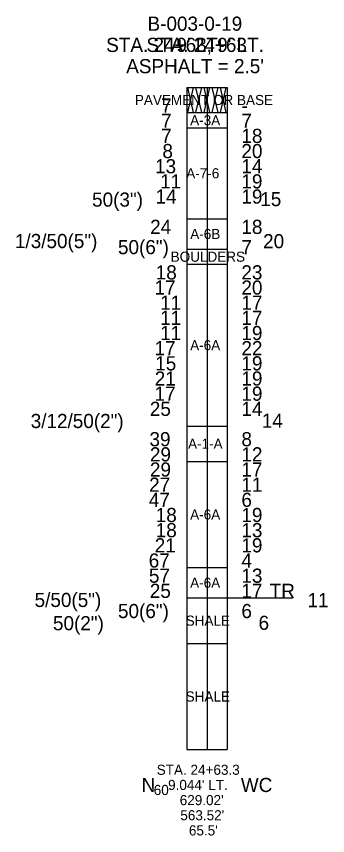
# Model space of a CAD drawing. Extents: x -1.89 to 1.19, y -7.4 to 0.7.
import ezdxf

# ---------------------------------------------------------------- set-up
doc = ezdxf.new("R2010")
doc.units = 0
for name, color, linetype in [('GT_Project_Soil_Boring', 7, 'Continuous'), ('GT_Project_Soil_Layers', 7, 'Continuous'), ('GT_Project_Text', 7, 'Continuous'), ('GT_Project_Text_2', 7, 'Continuous'), ('GT_Project_Text_3', 7, 'Continuous'), ('SC_Scratch1', 7, 'Continuous'), ('SC_Scratch2', 7, 'Continuous'), ('SC_Scratch3', 7, 'Continuous')]:
    doc.layers.add(name, color=color, linetype=linetype)

msp = doc.modelspace()

# ---------------------------------------------------------------- linework, layer by layer
at = {"layer": 'GT_Project_Soil_Boring'}
for points in [[(-0.2, 0), (0.2, 0)], [(-0.2, 0), (-0.2, -6.55)], [(0, 0), (0, -6.55)], [(0.2, 0), (0.2, -6.55)], [(-0.2, -0.25), (0.2, -0.25)], [(-0.2, -0.4), (0.2, -0.4)], [(-0.2, -1.3), (0.2, -1.3)], [(-0.2, -1.6), (0.2, -1.6)], [(-0.2, -1.75), (0.2, -1.75)], [(-0.2, -3.35), (0.2, -3.35)], [(-0.2, -3.7), (0.2, -3.7)], [(-0.2, -4.75), (0.2, -4.75)], [(-0.2, -5.05), (0.2, -5.05)], [(-0.2, -5.5), (0.2, -5.5)], [(-0.2, -6.55), (0.2, -6.55)]]:
    msp.add_lwpolyline(points, dxfattribs=at)
at = {"layer": 'GT_Project_Soil_Layers'}
for p, q in [((-0.1906, -0.25), (-0.1329, 0.0001)), ((-0.1329, -0.25), (-0.1906, 0.0001)), ((-0.1098, -0.25), (-0.052, 0.0001)), ((-0.052, -0.25), (-0.1098, 0.0001)), ((-0.0289, -0.25), (0.0288, 0.0001)), ((0.0288, -0.25), (-0.0289, 0.0001)), ((0.0519, -0.25), (0.1096, 0.0001)), ((0.1096, -0.25), (0.0519, 0.0001)), ((0.1327, -0.25), (0.1904, 0.0001)), ((0.1904, -0.25), (0.1327, 0.0001)), ((-0.2001, -0.25), (-0.2001, -0.25))]:
    msp.add_line(p, q, dxfattribs=at)
at = {"layer": 'GT_Project_Text'}
msp.add_line((-0.5272, -6.9), (-0.5272, -6.9), dxfattribs=at)
msp.add_lwpolyline([(0.2, -5.05), (0.85, -5.05)], dxfattribs=at)

# ---------------------------------------------------------------- texts
for s, height, p in [('B-003-0-19', 0.14, (-0.5886, 0.56)), ("ASPHALT = 2.5'", 0.14, (-0.7997, 0.14)), ('7', 0.14, (-0.4535, -0.25)), ('-', 0.14, (0.34, -0.25)), ('7', 0.14, (-0.4535, -0.4)), ('7', 0.14, (0.34, -0.4)), ('7', 0.14, (-0.4535, -0.55)), ('18', 0.14, (0.34, -0.55)), ('8', 0.14, (-0.4414, -0.7)), ('20', 0.14, (0.34, -0.7)), ('13', 0.14, (-0.5141, -0.85)), ('14', 0.14, (0.34, -0.85)), ('11', 0.14, (-0.4643, -1)), ('19', 0.14, (0.34, -1)), ('50(3")', 0.14, (-1.1372, -1.18)), ('14', 0.14, (-0.5097, -1.15)), ('19', 0.14, (0.34, -1.15)), ('15', 0.14, (0.5269, -1.175)), ('24', 0.14, (-0.5627, -1.45)), ('18', 0.14, (0.34, -1.45)), ('1/3/50(5")', 0.14, (-1.9005, -1.59)), ('20', 0.14, (0.5549, -1.5917)), ('50(6")', 0.14, (-0.8812, -1.65)), ('7', 0.14, (0.34, -1.65)), ('18', 0.14, (-0.5075, -1.9)), ('23', 0.14, (0.34, -1.9)), ('17', 0.14, (-0.5196, -2.05)), ('20', 0.14, (0.34, -2.05)), ('11', 0.14, (-0.4643, -2.2)), ('17', 0.14, (0.34, -2.2)), ('11', 0.14, (-0.4643, -2.35)), ('17', 0.14, (0.34, -2.35)), ('11', 0.14, (-0.4643, -2.5)), ('19', 0.14, (0.34, -2.5)), ('17', 0.14, (-0.5196, -2.65)), ('22', 0.14, (0.34, -2.65)), ('15', 0.14, (-0.513, -2.8)), ('19', 0.14, (0.34, -2.8)), ('21', 0.14, (-0.5173, -2.95)), ('19', 0.14, (0.34, -2.95)), ('17', 0.14, (-0.5196, -3.1)), ('19', 0.14, (0.34, -3.1)), ('25', 0.14, (-0.566, -3.25)), ('14', 0.14, (0.34, -3.25)), ('3/12/50(2")', 0.14, (-1.7445, -3.37)), ('14', 0.14, (0.5418, -3.3667)), ('39', 0.14, (-0.5693, -3.55)), ('8', 0.14, (0.34, -3.55)), ('29', 0.14, (-0.5649, -3.7)), ('12', 0.14, (0.34, -3.7)), ('29', 0.14, (-0.5649, -3.85)), ('17', 0.14, (0.34, -3.85)), ('27', 0.14, (-0.5726, -4)), ('11', 0.14, (0.34, -4)), ('47', 0.14, (-0.5759, -4.15)), ('6', 0.14, (0.34, -4.15)), ('18', 0.14, (-0.5075, -4.3)), ('19', 0.14, (0.34, -4.3)), ('18', 0.14, (-0.5075, -4.45)), ('13', 0.14, (0.34, -4.45)), ('21', 0.14, (-0.5173, -4.6)), ('19', 0.14, (0.34, -4.6)), ('67', 0.14, (-0.577, -4.75)), ('4', 0.14, (0.34, -4.75)), ('57', 0.14, (-0.5748, -4.9)), ('13', 0.14, (0.34, -4.9)), ('25', 0.14, (-0.566, -5.05)), ('17', 0.14, (0.34, -5.05)), ('TR', 0.14, (0.62, -5.05)), ('5/50(5")', 0.14, (-1.7059, -5.14)), ('11', 0.14, (0.994, -5.1417)), ('50(6")', 0.14, (-0.8812, -5.25)), ('6', 0.14, (0.34, -5.25)), ('50(2")', 0.14, (-1.5243, -5.37)), ('6', 0.14, (0.51, -5.3667)), ('N', 0.14, (-0.6473, -6.97)), ('WC', 0.14, (0.3345, -6.97)), ('60', 0.1, (-0.5272, -7))]:
    msp.add_text(s, height=height, dxfattribs=at).set_placement(p)
at = {"layer": 'GT_Project_Text_2'}
msp.add_text("9' LT.", height=0.14, dxfattribs=at).set_placement((-0.3031, 0.35))
at = {"layer": 'GT_Project_Text_3'}
msp.add_text('STA. 24+63', height=0.14, dxfattribs=at).set_placement((-0.5991, 0.35))
at = {"layer": 'SC_Scratch1'}
for s, p in [('PAVEMENT OR BASE', (-0.7139, -0.175)), ('A-3A', (-0.1668, -0.375)), ('A-7-6', (-0.2058, -0.9)), ('A-6B', (-0.166, -1.5)), ('BOULDERS', (-0.3596, -1.725)), ('A-6A', (-0.1668, -2.6)), ('A-1-A', (-0.1877, -3.575)), ('A-6A', (-0.1668, -4.275)), ('A-6A', (-0.1668, -4.95)), ('SHALE', (-0.2111, -5.325)), ('SHALE', (-0.2111, -6.075))]:
    msp.add_text(s, height=0.1, dxfattribs=at).set_placement(p)
at = {"layer": 'SC_Scratch2'}
for s, p in [('STA. 24+63.3', (-0.4977, -6.8)), ("9.044' LT.", (-0.3851, -6.95)), ("629.02'", (-0.2699, -7.1)), ("563.52'", (-0.2642, -7.25)), ("65.5'", (-0.1793, -7.4))]:
    msp.add_text(s, height=0.1, dxfattribs=at).set_placement(p)
at = {"layer": 'SC_Scratch3'}
msp.add_text("STA. 24+63, 9' LT.", height=0.14, dxfattribs=at).set_placement((-0.9976, 0.35))

doc.saveas('drawing.dxf')
